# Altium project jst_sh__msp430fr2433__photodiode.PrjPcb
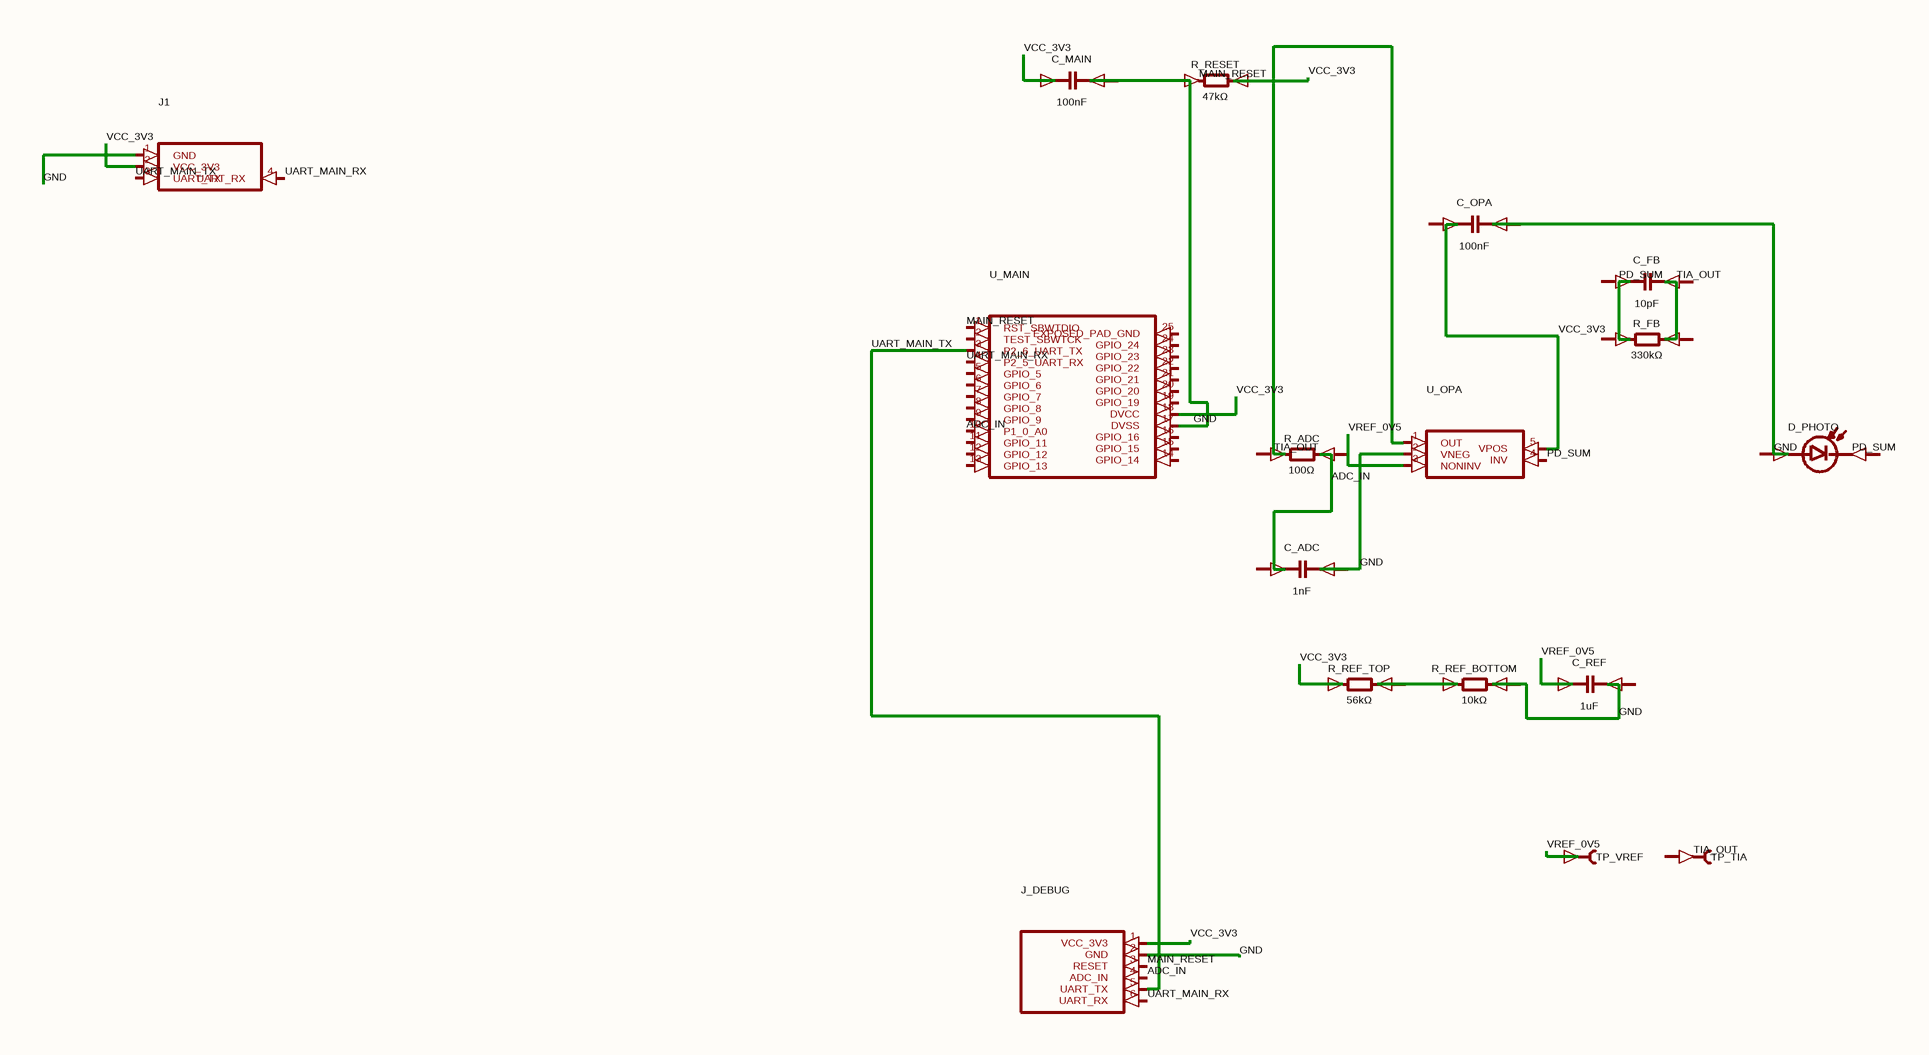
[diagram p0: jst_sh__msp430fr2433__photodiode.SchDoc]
1 sheet, 17 parts. Net scope: global (net labels, ports and power ports of the same name join across sheets).
Board file: jst_sh__msp430fr2433__photodiode.PcbDoc

## Sheet jst_sh__msp430fr2433__photodiode.SchDoc
size 212 x 135 mm

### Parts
C_ADC  1nF
C_FB  10pF
C_MAIN  100nF
C_OPA  100nF
C_REF  1uF
D_PHOTO  (no value)
J1  (no value)
J_DEBUG  (no value)
R_ADC  100Ω
R_FB  330kΩ
R_REF_BOTTOM  10kΩ
R_REF_TOP  56kΩ
R_RESET  47kΩ
TP_TIA  (no value)
TP_VREF  (no value)
U_MAIN  (no value)
U_OPA  (no value)

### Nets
ADC_IN: J_DEBUG.4(ADC_IN) U_MAIN.10(P1_0_A0)
GND: C_ADC.2(neg) C_MAIN.2(neg) C_OPA.2(neg) C_REF.1(pos) J1.1(GND) J_DEBUG.2(GND) R_ADC.2(cathode) R_REF_BOTTOM.2(cathode) R_RESET.1(anode) TP_VREF.1(pin1) U_MAIN.17(DVSS) U_OPA.2(VNEG) U_OPA.3(NONINV)  [also labelled VREF_0V5]
MAIN_RESET: J_DEBUG.3(RESET) U_MAIN.1(RST_SBWTDIO)
PD_SUM: U_OPA.4(INV)
TIA_OUT: U_OPA.1(OUT)
UART_MAIN_RX: J1.4(UART_RX) J_DEBUG.6(UART_RX) U_MAIN.4(P2_5_UART_RX)
UART_MAIN_TX: J1.3(UART_TX) J_DEBUG.5(UART_TX) U_MAIN.3(P2_6_UART_TX)
VCC_3V3: C_MAIN.1(pos) J1.2(VCC_3V3) J_DEBUG.1(VCC_3V3) R_REF_TOP.1(anode) R_RESET.2(cathode) U_MAIN.18(DVCC) U_OPA.5(VPOS)
NetR_REF_BOTTOM_1: R_REF_BOTTOM.1(anode) R_REF_TOP.2(cathode)

Not connected (* = marked no-connect by the designer): C_ADC 1(pos); C_FB 1(pos) 2(neg); C_OPA 1(pos); C_REF 2(neg); D_PHOTO 1(anode) 2(cathode); R_ADC 1(anode); R_FB 1(anode) 2(cathode); TP_TIA 1(pin1); U_MAIN 2(TEST_SBWTCK) 5(GPIO_5) 6(GPIO_6) 7(GPIO_7) 8(GPIO_8) 9(GPIO_9) 11(GPIO_11) 12(GPIO_12) 13(GPIO_13) 14(GPIO_14) 15(GPIO_15) 16(GPIO_16) 19(GPIO_19) 20(GPIO_20) 21(GPIO_21) 22(GPIO_22) 23(GPIO_23) 24(GPIO_24) 25(EXPOSED_PAD_GND)

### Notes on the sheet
- Labels drawn without touching a wire or pin: MAIN_RESET, PD_SUM, TIA_OUT

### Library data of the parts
C_ADC C_FB C_MAIN C_OPA C_REF = capacitor_right
D_PHOTO = photodiode_horz
J1 = J1
J_DEBUG = J_DEBUG
R_ADC R_FB R_REF_BOTTOM R_REF_TOP R_RESET = boxresistor_right
TP_TIA TP_VREF = testpoint_right
U_MAIN = U_MAIN
U_OPA = U_OPA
